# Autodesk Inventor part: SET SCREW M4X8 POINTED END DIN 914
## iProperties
IsCustomPart: 1
Created: 2006-02
Part Number: SET SCREW M4X8 POINTED END DIN 914
Material: Steel, Mild
Description: Hexagon Socket Set Screw
Document SubType Name: Modeling
Standard: DIN 914
Designer: Andy Moles
Standards Organization: DIN
Language: en-US
Size Designation: M4 x 8
Categories: <MemberInstance><Categories><Category DisplayName="Fasteners" InternalName="e4da775c-781d-43d5-af7c-5136215cf5a6" Mnemonic="FSTN"><Category DisplayName="Bolts"
Density: 1 g/cm^3
Author: Andy Moles
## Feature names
1. Body [Revolution]
2. Slot [Extrusion]
3. Chamfer1
4. Chamfer2
